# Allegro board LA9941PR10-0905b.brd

Outline 291.1 x 129.75 mm; copper layers: TOP, GND1, IN1, VCC, IN2, IN3, GND2, IN4, GND3, BOTTOM. Coordinates in mm from the lower left corner of the outline.

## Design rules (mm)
net group 8: nets DISP_CEC DISPOFF#
net group 10: nets AUD_SPK_L+ AUD_SPK_R+
net group AC: nets ACN ACP
net group CLK_27M: nets CLK_27M_IN CLK_27M_OUT
net group CSO_B: nets CSON_B CSOP_B
net group CSS_1: nets CSSN_1 CSSP_1
net group DDRA_CTRL: nets DDR_CS0_DIMMA# DDR_CS1_DIMMA#
net group DIFFPAIR0: nets DDC_CLK_HDMI DDC_DAT_HDMI
net group DIFFPAIR32: nets MDP_A3N_CPU MDP_A3P_CPU
net group DIFFPAIR33: nets MDP_A2N_CPU MDP_A2P_CPU
net group DIFFPAIR34: nets MDP_A1N_CPU MDP_A1P_CPU
net group DISP_C_A1: nets DISP_C_A1N DISP_C_A1P
net group DISP_C_A2: nets DISP_C_A2N DISP_C_A2P
net group DISP_C_A3: nets DISP_C_A3N DISP_C_A3P
net group EC_SMB_DA1: nets EC_SMB_CK1 EC_SMB_DA1
net group EDP_TX2: nets EDP_TXN2 EDP_TXP2
net group EDP_TX2_C: nets EDP_TXN2_C EDP_TXP2_C
net group EDP_TX2_R: nets EDP_TXN2_R EDP_TXP2_R
net group EDP_TX3: nets EDP_TXN3 EDP_TXP3
net group EDP_TX3_C: nets EDP_TXN3_C EDP_TXP3_C
net group EDP_TX3_R: nets EDP_TXN3_R EDP_TXP3_R
net group ISUM: nets ISUMN ISUMP
net group MDP_A0_R: nets MDP_A0N_R MDP_A0P_R
net group MDP_A1_R: nets MDP_A1N_R MDP_A1P_R
net group MDP_A2_R: nets MDP_A2N_R MDP_A2P_R
net group MDP_A3_R: nets MDP_A3N_R MDP_A3P_R
net group PCH_SMBCLK: nets PCH_SMBCLK PCH_SMBDATA
net group SR: nets SRN SRP
net group USB3R1_8723: nets USB3RN1_8723 USB3RP1_8723
net group USB3R1_C: nets USB3RN1_C USB3RP1_C
net group USB3R2_8723: nets USB3RN2_8723 USB3RP2_8723
net group USB3R2_C: nets USB3RN2_C USB3RP2_C
net group USB3RN4: nets USB3RN4 USB3RP4
net group USB3T1_8723: nets USB3TN1_8723 USB3TP1_8723
net group USB3T1_C: nets USB3TN1_C USB3TP1_C
net group USB3T2_8723: nets USB3TN2_8723 USB3TP2_8723
net group USB3T2_C: nets USB3TN2_C USB3TP2_C
net group USB3TN4: nets USB3TN4 USB3TP4
net group VSSSEN: nets VCCSENSE VSSSENSE
net group 15: nets CLK_CPU_ITP CLK_CPU_ITP# CLK_PCIE_CD CLK_PCIE_CD# CLK_PCIE_MINI3 CLK_PCIE_MINI3# CLKIN_DMI CLKIN_DMI# CLKIN_DOT96 CLKIN_DOT96# CLKIN_SATA CLKIN_SATA# EDP_COMP EDP_HPD EDP_HPD_S EDP_LVDDEN EDP_PWM FDI_INT TMDS_L_TXCP USBRBIAS
net group 20: nets SPK_L+ SPK_L- SPK_R+ SPK_R-
net group 50H: nets CLK_PCH_14M DDR_A_D0 DDR_A_D1 DDR_A_D2 DDR_A_D3 DDR_A_D4 DDR_A_D5 DDR_A_D6 DDR_A_D7 DDR_A_D8 DDR_A_D9 DDR_A_D10 DDR_A_D11 DDR_A_D12 DDR_A_D13 DDR_A_D14 DDR_A_D15 DDR_A_D16 DDR_A_D17 DDR_A_D18 DDR_A_D19 DDR_A_D20 DDR_A_D21 DDR_A_D22 DDR_A_D23 DDR_A_D24 DDR_A_D25 DDR_A_D26 DDR_A_D27 DDR_A_D28 DDR_A_D29 DDR_A_D30 DDR_A_D31 DDR_A_D32 DDR_A_D33 DDR_A_D34 DDR_A_D35 DDR_A_D36 DDR_A_D37 DDR_A_D38 DDR_A_D39 DDR_A_D40 DDR_A_D41 DDR_A_D42 DDR_A_D43 DDR_A_D44 DDR_A_D45 DDR_A_D46 DDR_A_D47 DDR_A_D48 DDR_A_D49 DDR_A_D50 DDR_A_D51 DDR_A_D52 DDR_A_D53 DDR_A_D54 DDR_A_D55 DDR_A_D56 DDR_A_D57 DDR_A_D58 DDR_A_D59 DDR_A_D60 DDR_A_D61 DDR_A_D62 DDR_A_D63 DDR_B_D0 DDR_B_D1 DDR_B_D2 DDR_B_D3 DDR_B_D4 DDR_B_D5 DDR_B_D6 DDR_B_D7 DDR_B_D8 DDR_B_D9 DDR_B_D10 DDR_B_D11 DDR_B_D12 DDR_B_D13 DDR_B_D14 DDR_B_D15 DDR_B_D16 DDR_B_D17 DDR_B_D18 DDR_B_D19 DDR_B_D20 DDR_B_D21 DDR_B_D22 DDR_B_D23 DDR_B_D24 DDR_B_D25 DDR_B_D26 DDR_B_D27 DDR_B_D28 DDR_B_D29 DDR_B_D30 DDR_B_D31 DDR_B_D32 DDR_B_D33 DDR_B_D34 DDR_B_D35 DDR_B_D36 DDR_B_D37 DDR_B_D38 DDR_B_D39 DDR_B_D40 DDR_B_D41 DDR_B_D42 DDR_B_D43 DDR_B_D44 DDR_B_D45 DDR_B_D46 DDR_B_D47 DDR_B_D48 DDR_B_D49 DDR_B_D50 DDR_B_D51 DDR_B_D52 DDR_B_D53 DDR_B_D54 DDR_B_D55 DDR_B_D56 DDR_B_D57 DDR_B_D58 DDR_B_D59 DDR_B_D60 DDR_B_D61 DDR_B_D62 DDR_B_D63 DSWODVREN H_CPU_SVIDALRT# H_PROCHOT#_EC H_PROCHOT#_R H_THERMTRIP#_C HDA_BIT_CLK HDA_BITCLK_AUDIO HDA_RST# HDA_RST_AUDIO# HDA_SDIN0 HDA_SDO HDA_SDOUT HDA_SDOUT_AUDIO HDA_SPKR HDA_SYNC HDA_SYNC_AUDIO KB_RST# LPC_AD0 LPC_AD1 LPC_AD2 LPC_AD3 LPC_FRAME# PBTN_OUT# PCH_INTVRMEN PCH_RSMRST# PCH_SPI_CS1# PCH_SPI_HOLD# PCH_SPI_WP# SM_INTRUDER# SYS_PWROK WAKE# XDP_DBRESET#
net group ASY: nets CPU_PLTRST# H_CPUPWRGD H_PM_SYNC H_PROCHOT# H_THERMTRIP# PM_DRAM_PWRGD PM_SYS_PWRGD_BUF PM_SYS_PWRGD_BUF_R
net group DDR-CMD/CTL_12/18: nets DDR_A_BS0 DDR_A_BS1 DDR_A_BS2 DDR_A_CAS# DDR_A_MA0 DDR_A_MA1 DDR_A_MA2 DDR_A_MA3 DDR_A_MA4 DDR_A_MA5 DDR_A_MA6 DDR_A_MA7 DDR_A_MA8 DDR_A_MA9 DDR_A_MA10 DDR_A_MA11 DDR_A_MA12 DDR_A_MA13 DDR_A_MA14 DDR_A_MA15 DDR_A_RAS# DDR_A_WE# DDR_B_BS0 DDR_B_BS1 DDR_B_BS2 DDR_B_CAS# DDR_B_MA0 DDR_B_MA1 DDR_B_MA2 DDR_B_MA3 DDR_B_MA4 DDR_B_MA5 DDR_B_MA6 DDR_B_MA7 DDR_B_MA8 DDR_B_MA9 DDR_B_MA10 DDR_B_MA11 DDR_B_MA12 DDR_B_MA13 DDR_B_MA14 DDR_B_MA15 DDR_B_RAS# DDR_B_WE# DDR_CKE0_DIMMA DDR_CKE1_DIMMA DDR_CKE2_DIMMB DDR_CKE3_DIMMB DDR_CS2_DIMMB# DDR_CS3_DIMMB# M_ODT0 M_ODT1 M_ODT2 M_ODT3
net group DDR_CLK: nets M_CLK_DDR0 M_CLK_DDR1 M_CLK_DDR2 M_CLK_DDR3 M_CLK_DDR#0 M_CLK_DDR#1 M_CLK_DDR#2 M_CLK_DDR#3
net group DDR_DQS: nets DDR_A_DQS0 DDR_A_DQS1 DDR_A_DQS2 DDR_A_DQS3 DDR_A_DQS4 DDR_A_DQS5 DDR_A_DQS6 DDR_A_DQS7 DDR_A_DQS#0 DDR_A_DQS#1 DDR_A_DQS#2 DDR_A_DQS#3 DDR_A_DQS#4 DDR_A_DQS#5 DDR_A_DQS#6 DDR_A_DQS#7 DDR_B_DQS0 DDR_B_DQS1 DDR_B_DQS2 DDR_B_DQS3 DDR_B_DQS4 DDR_B_DQS5 DDR_B_DQS6 DDR_B_DQS7 DDR_B_DQS#0 DDR_B_DQS#1 DDR_B_DQS#2 DDR_B_DQS#3 DDR_B_DQS#4 DDR_B_DQS#5 DDR_B_DQS#6 DDR_B_DQS#7
net group DIFFPAIR35: nets MDP_A0P_CPU
net group DMI: nets DMI_CRX_PTX_N0 DMI_CRX_PTX_N1 DMI_CRX_PTX_N2 DMI_CRX_PTX_N3 DMI_CRX_PTX_P0 DMI_CRX_PTX_P1 DMI_CRX_PTX_P2 DMI_CRX_PTX_P3 DMI_CTX_PRX_N0 DMI_CTX_PRX_N1 DMI_CTX_PRX_N2 DMI_CTX_PRX_N3 DMI_CTX_PRX_P0 DMI_CTX_PRX_P1 DMI_CTX_PRX_P2 DMI_CTX_PRX_P3
net group DP: nets DISP_A0N_R DISP_A0P_R DISP_A1N_R DISP_A1P_R DISP_A2N_R DISP_A2P_R DISP_A3N_R DISP_A3P_R DISP_C_A0N DISP_C_A0P DISP_CLK_AUXP_CONN DISP_DAT_AUXN_CONN MDP_A0N_CPU MDP_AUXN_PCH MDP_AUXN_PCH_C MDP_AUXP_PCH MDP_AUXP_PCH_C
net group EDP: nets EDP_AUXN EDP_AUXN_R EDP_AUXP EDP_AUXP_R EDP_TXN0 EDP_TXN0_C EDP_TXN0_R EDP_TXN1 EDP_TXN1_C EDP_TXN1_R EDP_TXP0 EDP_TXP0_C EDP_TXP0_R EDP_TXP1 EDP_TXP1_C EDP_TXP1_R
net group GREEN CLK: nets XTAL25_IN
net group HDMI: nets HDMI_A0N_VGA HDMI_A0P_VGA HDMI_A1N_VGA HDMI_A1P_VGA HDMI_A2N_VGA HDMI_A2P_VGA HDMI_A3N_VGA HDMI_A3P_VGA HDMI_CEC HDMI_DDB_CTRLCLK HDMI_DDB_CTRLDATA HDMI_HPLUG HDMI_RESERVED TMDS_L_TX0N TMDS_L_TX0P TMDS_L_TX1N TMDS_L_TX1P TMDS_L_TX2N TMDS_L_TX2P TMDS_L_TXCN TMDS_RD_TX0N TMDS_RD_TX0P TMDS_RD_TX1N TMDS_RD_TX1P TMDS_RD_TX2N TMDS_RD_TX2P TMDS_RD_TXCN TMDS_RD_TXCP TMDS_TX0N TMDS_TX0P TMDS_TX1N TMDS_TX1P TMDS_TX2N TMDS_TX2P TMDS_TXCN TMDS_TXCP
net group KB: nets KB_CAPS_LED KB_DET# KSI0 KSI1 KSI2 KSI3 KSI4 KSI5 KSI6 KSI7 KSO0 KSO1 KSO2 KSO3 KSO4 KSO5 KSO6 KSO7 KSO8 KSO9 KSO10 KSO11 KSO12 KSO13 KSO14 KSO15 KSO16
net group PCIE: nets PCIE_PRX_CARDTX_N4 PCIE_PRX_CARDTX_P4 PCIE_PRX_WLANTX_N3 PCIE_PRX_WLANTX_P3 PCIE_PTX_CARDRX_N4 PCIE_PTX_CARDRX_N4_C PCIE_PTX_CARDRX_P4 PCIE_PTX_CARDRX_P4_C PCIE_PTX_WLANRX_N3 PCIE_PTX_WLANRX_N3_C PCIE_PTX_WLANRX_P3 PCIE_PTX_WLANRX_P3_C
net group PECI: nets H_PECI
net group PEG: nets PEG_GTX_C_HRX_N0 PEG_GTX_C_HRX_N1 PEG_GTX_C_HRX_N2 PEG_GTX_C_HRX_N3 PEG_GTX_C_HRX_N4 PEG_GTX_C_HRX_N5 PEG_GTX_C_HRX_N6 PEG_GTX_C_HRX_N7 PEG_GTX_C_HRX_N8 PEG_GTX_C_HRX_N9 PEG_GTX_C_HRX_N10 PEG_GTX_C_HRX_N11 PEG_GTX_C_HRX_N12 PEG_GTX_C_HRX_N13 PEG_GTX_C_HRX_N14 PEG_GTX_C_HRX_N15 PEG_GTX_C_HRX_P0 PEG_GTX_C_HRX_P1 PEG_GTX_C_HRX_P2 PEG_GTX_C_HRX_P3 PEG_GTX_C_HRX_P4 PEG_GTX_C_HRX_P5 PEG_GTX_C_HRX_P6 PEG_GTX_C_HRX_P7 PEG_GTX_C_HRX_P8 PEG_GTX_C_HRX_P9 PEG_GTX_C_HRX_P10 PEG_GTX_C_HRX_P11 PEG_GTX_C_HRX_P12 PEG_GTX_C_HRX_P13 PEG_GTX_C_HRX_P14 PEG_GTX_C_HRX_P15 PEG_GTX_HRX_N0 PEG_GTX_HRX_N1 PEG_GTX_HRX_N2 PEG_GTX_HRX_N3 PEG_GTX_HRX_N4 PEG_GTX_HRX_N5 PEG_GTX_HRX_N6 PEG_GTX_HRX_N7 PEG_GTX_HRX_N8 PEG_GTX_HRX_N9 PEG_GTX_HRX_N10 PEG_GTX_HRX_N11 PEG_GTX_HRX_N12 PEG_GTX_HRX_N13 PEG_GTX_HRX_N14 PEG_GTX_HRX_N15 PEG_GTX_HRX_P0 PEG_GTX_HRX_P1 PEG_GTX_HRX_P2 PEG_GTX_HRX_P3 PEG_GTX_HRX_P4 PEG_GTX_HRX_P5 PEG_GTX_HRX_P6 PEG_GTX_HRX_P7 PEG_GTX_HRX_P8 PEG_GTX_HRX_P9 PEG_GTX_HRX_P10 PEG_GTX_HRX_P11 PEG_GTX_HRX_P12 PEG_GTX_HRX_P13 PEG_GTX_HRX_P14 PEG_GTX_HRX_P15 PEG_HTX_C_GRX_N0 PEG_HTX_C_GRX_N1 PEG_HTX_C_GRX_N2 PEG_HTX_C_GRX_N3 PEG_HTX_C_GRX_N4 PEG_HTX_C_GRX_N5 PEG_HTX_C_GRX_N6 PEG_HTX_C_GRX_N7 PEG_HTX_C_GRX_N8 PEG_HTX_C_GRX_N9 PEG_HTX_C_GRX_N10 PEG_HTX_C_GRX_N11 PEG_HTX_C_GRX_N12 PEG_HTX_C_GRX_N13 PEG_HTX_C_GRX_N14 PEG_HTX_C_GRX_N15 PEG_HTX_C_GRX_P0 PEG_HTX_C_GRX_P1 PEG_HTX_C_GRX_P2 PEG_HTX_C_GRX_P3 PEG_HTX_C_GRX_P4 PEG_HTX_C_GRX_P5 PEG_HTX_C_GRX_P6 PEG_HTX_C_GRX_P7 PEG_HTX_C_GRX_P8 PEG_HTX_C_GRX_P9 PEG_HTX_C_GRX_P10 PEG_HTX_C_GRX_P11 PEG_HTX_C_GRX_P12 PEG_HTX_C_GRX_P13 PEG_HTX_C_GRX_P14 PEG_HTX_C_GRX_P15 PEG_HTX_GRX_N0 PEG_HTX_GRX_N1 PEG_HTX_GRX_N2 PEG_HTX_GRX_N3 PEG_HTX_GRX_N4 PEG_HTX_GRX_N5 PEG_HTX_GRX_N6 PEG_HTX_GRX_N7 PEG_HTX_GRX_N8 PEG_HTX_GRX_N9 PEG_HTX_GRX_N10 PEG_HTX_GRX_N11 PEG_HTX_GRX_N12 PEG_HTX_GRX_N13 PEG_HTX_GRX_N14 PEG_HTX_GRX_N15 PEG_HTX_GRX_P0 PEG_HTX_GRX_P1 PEG_HTX_GRX_P2 PEG_HTX_GRX_P3 PEG_HTX_GRX_P4 PEG_HTX_GRX_P5 PEG_HTX_GRX_P6 PEG_HTX_GRX_P7 PEG_HTX_GRX_P8 PEG_HTX_GRX_P9 PEG_HTX_GRX_P10 PEG_HTX_GRX_P11 PEG_HTX_GRX_P12 PEG_HTX_GRX_P13 PEG_HTX_GRX_P14 PEG_HTX_GRX_P15
net group PLATFORM CLK: nets CLK_CPU_DMI CLK_CPU_DMI# CLK_CPU_SSC_DPLL CLK_CPU_SSC_DPLL# CLK_PCI0 CLK_PCI1 CLK_PCI2 CLK_PCI_DEBUG CLK_PCI_LPBACK CLK_PCI_LPC CLK_PCI_TPM CLK_PCI_TPM_R CLK_PEG_VGA CLK_PEG_VGA# DPLL_REF_CLK DPLL_REF_CLK#
net group PWR: nets +0.675VS +0.675VSP +1.2V_5505SWR +1.2V_5505SWR_S +1.5V_RUN_B+ +1.05VM_VCCASW +1.05VM_VCCSUS1 +1.05VM_VCCSUS2 +1.5VS +1.05VS_VCCCORE +1.05VSDGPU +1.5VSDGPU +1.35V +1.35V_CPU_VDDQ +1.35V_MEN_P +1.35V_PWROK +2.5V_5505LDO_S +3.3V_RUN_VDD33 +3V_MSATA +3V_NFC +3V_PCH +3V_PS8723 +3V_THERMAL +3V_VCCPSPI +3VALW +3VALW_EC +3VALWP +3VLP +3VS_DELAY +3VS_DP +3VS_MDPR +5V_HDMI_DDC +5VALWP +5VS_HDD +5VS_KBL +CLK_PLLVDD +EC_VCCA +EDPVDD +FB_VREF +FBA_PLL_AVDD +FBA_VREFC_H +FBA_VREFC_L +FBA_VREFD_H +FBA_VREFD_L +FBB_VREFC_H +FBB_VREFC_L +FBB_VREFD_H +FBB_VREFD_L +INV_PWR_SRC +LCDVDD_R +MIC1_VREFO +PCH_USB_DCPSUS3 +PCH_VCC +PCH_VCCASW +PCH_VCCCFUSE +PCH_VCCCLK +PCH_VCCCLK3_3 +PCH_VCCDSW +PCH_VCCDSW_R +PCH_VPROC +PLLVDD +RTCBATT +RTCVCC +V1.05S_VCCP_PWRGOOD +V1.05V_B+ +V18R +V_DDR_REF +V_DDR_REFA_R +V_DDR_REFB_R +V_SM_VREF +VCC_PWR_SRC1 +VCC_PWR_SRC2 +VCCAFDI_VRM +VCCIO2PCH +VCCIO_OUT +VCCIOA_OUT +VCCRTCEXT +VCCSST +VCHGR +VDDA +VDISPLAY_VCC +VGA_B+ +VLDOIN_1.35V +VSBP +VSBP_AMP_AVCC +VSBP_AMP_PVCC
net group RTC: nets PCH_RTCRST# PCH_RTCX1 PCH_RTCX2 PCH_SRTCRST#
net group SATA: nets SATA_PRX_DTX_N0 SATA_PRX_DTX_N0_C SATA_PRX_DTX_N0_RC SATA_PRX_DTX_N0_RC1 SATA_PRX_DTX_N1 SATA_PRX_DTX_P0 SATA_PRX_DTX_P0_C SATA_PRX_DTX_P0_RC SATA_PRX_DTX_P0_RC1 SATA_PRX_DTX_P1 SATA_PTX_DRX_N0 SATA_PTX_DRX_N0_C SATA_PTX_DRX_N0_RC SATA_PTX_DRX_N0_RC1 SATA_PTX_DRX_N1 SATA_PTX_DRX_N1_C SATA_PTX_DRX_P0 SATA_PTX_DRX_P0_C SATA_PTX_DRX_P0_RC SATA_PTX_DRX_P0_RC1 SATA_PTX_DRX_P1 SATA_PTX_DRX_P1_C
net group SPI: nets PCH_SPI_CLK PCH_SPI_CS# PCH_SPI_SI PCH_SPI_SO
net group SVID: nets VR_SVID_ALRT# VR_SVID_CLK VR_SVID_DAT
net group USB2.0: nets USB20_N0 USB20_N1 USB20_N2 USB20_N3 USB20_N4 USB20_N9 USB20_N9_R USB20_N12 USB20_P0 USB20_P1 USB20_P2 USB20_P3 USB20_P4 USB20_P9_R USB20_P12 USBP0_D+ USBP0_D- USBP0_R_D+ USBP0_R_D- USBP1_D+ USBP1_D- USBP1_R_D+ USBP1_R_D-
net group USB3.0: nets USB3RN1 USB3RN1_D- USB3RN2 USB3RN2_D- USB3RN3 USB3RP1 USB3RP1_D+ USB3RP2 USB3RP2_D+ USB3RP3 USB3T_N1 USB3T_N2 USB3T_P1 USB3T_P2 USB3TN1 USB3TN1_D- USB3TN2 USB3TN2_D- USB3TN3 USB3TP1 USB3TP1_D+ USB3TP2 USB3TP2_D+ USB3TP3
net group USB20_N9: nets USB20_P9
net group VRAM-CMD_10_25: nets FBA_CMD0 FBA_CMD1 FBA_CMD2 FBA_CMD3 FBA_CMD4 FBA_CMD5 FBA_CMD6 FBA_CMD7 FBA_CMD8 FBA_CMD9 FBA_CMD10 FBA_CMD11 FBA_CMD12 FBA_CMD13 FBA_CMD14 FBA_CMD15 FBA_CMD16 FBA_CMD17 FBA_CMD18 FBA_CMD19 FBA_CMD20 FBA_CMD21 FBA_CMD22 FBA_CMD23 FBA_CMD24 FBA_CMD25 FBA_CMD26 FBA_CMD27 FBA_CMD28 FBA_CMD29 FBA_CMD30 FBA_CMD31 FBB_CMD0 FBB_CMD1 FBB_CMD2 FBB_CMD3 FBB_CMD4 FBB_CMD5 FBB_CMD6 FBB_CMD7 FBB_CMD8 FBB_CMD9 FBB_CMD10 FBB_CMD11 FBB_CMD12 FBB_CMD13 FBB_CMD14 FBB_CMD15 FBB_CMD16 FBB_CMD17 FBB_CMD18 FBB_CMD19 FBB_CMD20 FBB_CMD21 FBB_CMD22 FBB_CMD23 FBB_CMD24 FBB_CMD25 FBB_CMD26 FBB_CMD27 FBB_CMD28 FBB_CMD29 FBB_CMD30 FBB_CMD31
net group VRAM-DQ/CLK_10_25: nets CLKA0 CLKA0# CLKA1 CLKA1# CLKB0 CLKB0# CLKB1 CLKB1# FBA_D0 FBA_D1 FBA_D2 FBA_D3 FBA_D4 FBA_D5 FBA_D6 FBA_D7 FBA_D8 FBA_D9 FBA_D10 FBA_D11 FBA_D12 FBA_D13 FBA_D14 FBA_D15 FBA_D16 FBA_D17 FBA_D18 FBA_D19 FBA_D20 FBA_D21 FBA_D22 FBA_D23 FBA_D24 FBA_D25 FBA_D26 FBA_D27 FBA_D28 FBA_D29 FBA_D30 FBA_D31 FBA_D32 FBA_D33 FBA_D34 FBA_D35 FBA_D36 FBA_D37 FBA_D38 FBA_D39 FBA_D40 FBA_D41 FBA_D42 FBA_D43 FBA_D44 FBA_D45 FBA_D46 FBA_D47 FBA_D48 FBA_D49 FBA_D50 FBA_D51 FBA_D52 FBA_D53 FBA_D54 FBA_D55 FBA_D56 FBA_D57 FBA_D58 FBA_D59 FBA_D60 FBA_D61 FBA_D62 FBA_D63 FBA_DBI0 FBA_DBI1 FBA_DBI2 FBA_DBI3 FBA_DBI4 FBA_DBI5 FBA_DBI6 FBA_DBI7 FBA_EDC0 FBA_EDC1 FBA_EDC2 FBA_EDC3 FBA_EDC4 FBA_EDC5 FBA_EDC6 FBA_EDC7 FBB_D0 FBB_D1 FBB_D2 FBB_D3 FBB_D4 FBB_D5 FBB_D6 FBB_D7 FBB_D8 FBB_D9 FBB_D10 FBB_D11 FBB_D12 FBB_D13 FBB_D14 FBB_D15 FBB_D16 FBB_D17 FBB_D18 FBB_D19 FBB_D20 FBB_D21 FBB_D22 FBB_D23 FBB_D24 FBB_D25 FBB_D26 FBB_D27 FBB_D28 FBB_D29 FBB_D30 FBB_D31 FBB_D32 FBB_D33 FBB_D34 FBB_D35 FBB_D36 FBB_D37 FBB_D38 FBB_D39 FBB_D40 FBB_D41 FBB_D42 FBB_D43 FBB_D44 FBB_D45 FBB_D46 FBB_D47 FBB_D48 FBB_D49 FBB_D50 FBB_D51 FBB_D52 FBB_D53 FBB_D54 FBB_D55 FBB_D56 FBB_D57 FBB_D58 FBB_D59 FBB_D60 FBB_D61 FBB_D62 FBB_D63 FBB_DBI0 FBB_DBI1 FBB_DBI2 FBB_DBI3 FBB_DBI4 FBB_DBI5 FBB_DBI6 FBB_DBI7 FBB_EDC0 FBB_EDC1 FBB_EDC2 FBB_EDC3 FBB_EDC4 FBB_EDC5 FBB_EDC6 FBB_EDC7
net group VRAM-WCK_15/10_25: nets FBA_WCK01 FBA_WCK01# FBA_WCK23 FBA_WCK23# FBA_WCK45 FBA_WCK45# FBA_WCK67 FBA_WCK67# FBB_WCK23 FBB_WCK23# FBB_WCK45 FBB_WCK45# FBB_WCK67 FBB_WCK67#
nets with their own width: min track width 0.254; nets BAT1 BAT2 BAT3 BAT4 BAT5 BATT_LOW_LED#_D GPU_VDD_SENSE GPU_VSS_SENSE IBAT1 IBAT2 IBAT3 IBAT4 IBAT5 SENSE_B#
nets with their own width: min track width 0.305; nets PEG_COMP
nets with their own width: min track width 0.381; nets SM_RCOMP0 SM_RCOMP1 SM_RCOMP2
nets with their own width: min track width 0.508; nets +3VS_RD +5VALW +5VS +FBA_DLL_AVDD +GPU_CORE +VCC_CORE +VCCP AGND B+ B++ ECAGND GND KB_BL_PWM N6647607 N97573639 N98184072 N112583857 N114414277 VIN
nets with their own width: min track width 1.524; nets +3VS N112208327
nets with their own width: min track width 2.032; nets +5V_CHGUSB_1 +5V_CHGUSB_3

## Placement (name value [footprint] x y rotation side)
ADP100  -  [ACES_50290-00701-001_7P-T]  22.9 92.06 0 bottom
BAT100  -  [ACES_50290-01201-P01_12P-T]  108.4 20.14 180 bottom
C1  -  [C_0402]  198.2 17.56 180 top
C2  -  [C_0402]  198.2 18.45 180 top
C3  -  [C_0402]  198 13.85 180 top
C4  -  [C_0402]  207.77 14.5 270 top
C5  -  [C_0402]  207.89 17.62 0 top
C6  -  [C_0402]  208.42 20.45 180 top
C8  -  [C_0402]  207.89 16.48 0 top
C11  -  [C_0603]  217.04 21.8 180 bottom
C12  -  [C_0603]  226.06 23.06 270 bottom
C13  -  [C_0402]  218.31 20.51 90 top
C14  -  [C_0402]  218.31 22.66 90 top
C15  -  [C_0402]  215.01 21.42 270 top
C16  -  [C_0402]  215.01 22.66 90 top
C17  -  [C_0402]  10.07 84.35 90 top
C18  -  [C_0402]  9.17 86.14 0 top
C37  -  [C_0402]  26.95 80.91 0 top
C38  -  [C_0402]  30.4 77.74 180 top
C42  -  [C_0402]  29.72 84.16 270 bottom
C43  -  [C_0402]  25.18 75.27 270 top
C47  -  [C_0402]  30.61 84.16 270 bottom
C48  -  [C_0402]  30.4 80.72 180 top
C53  -  [C_0402]  28.83 84.16 270 bottom
C54  -  [C_0402]  22 83.07 0 bottom
C56  -  [C_0402]  22 82.18 0 bottom
C57  -  [C_0402]  22 84.02 0 bottom
C59  -  [C_0402]  22 84.98 0 bottom
C93  -  [C_0402]  31.5 84.16 270 bottom
C1135  -  [C_0402]  122.49 21.08 90 bottom
C2020  -  [C_0402]  25.18 76.14 90 top
C2021  -  [C_0402]  30.39 76.67 270 top
CA3  -  [C_0805]  33.58 36.46 0 top
CA4  -  [C_0402]  34.38 38.41 0 top
CA5  -  [C_0805]  19.56 51.26 180 top
CA6  -  [C_0402]  19.89 45.54 180 top
CA7  -  [C_0402]  28.92 41.16 180 bottom
CA8  -  [C_0603]  26.45 44.4 90 bottom
CA9  -  [C_0402]  27.53 45.24 270 bottom
CA10  -  [C_0402]  23.43 38.54 90 bottom
CA11  -  [C_0603]  22.29 40.08 270 bottom
CA12  -  [C_0805]  19.56 53.04 180 top
CA13  -  [C_0402]  22.67 46.49 0 bottom
CA14  -  [C_0805]  19.34 39.4 270 top
CA15  -  [C_0402]  23.01 45.16 0 bottom
CA16  -  [C_0603]  23.11 36.58 0 top
CA17  -  [C_0402]  29.86 39.11 0 top
CA18  -  [C_0805]  25.37 39 0 bottom
CA19  -  [C_0402]  24.32 38.54 90 bottom
CA20  -  [C_0402]  24.41 46.49 0 bottom
CA21  -  [C_0805]  26.37 43 0 bottom
CA22  -  [C_0402]  5.45 35.69 0 top
CA23  -  [C_0402]  31.65 45.16 0 top
CA24  -  [C_0402]  26.42 36.97 270 top
CA25  -  [C_0402]  25.53 36.97 270 top
CA26  -  [C_B2]  20.08 39.58 270 bottom
CA27  -  [C_0402]  31.65 43.89 0 top
CA28  -  [C_0402]  9.32 34.77 0 bottom
CA29  -  [C_0402]  9.32 33.73 0 bottom
CA30  -  [C_0402]  31.72 35.57 180 top
CA31  -  [C_0805]  7.54 32.67 0 top
CA32  -  [C_0402]  29.73 38.23 0 bottom
CA33  -  [C_0402]  14.86 37.22 0 top
CA34  -  [C_0402]  17.72 45.99 180 top
CA37  -  [C_0402]  17.55 37.22 180 top
CA38  -  [C_0402]  15.05 45.99 0 top
CA39  -  [C_0402]  31.43 40.95 180 top
CA41  -  [C_0402]  3.4 22.5 270 bottom
CA42  -  [C_0402]  4.29 22.5 270 bottom
CA43  -  [C_0805]  13.31 20.49 270 top
CA45  -  [C_0805]  9.69 20.56 90 top
CA46  -  [C_0805]  7.91 20.56 90 top
CA53  -  [C_0402]  6.98 31.33 270 bottom
CA54  -  [C_0603]  6.6 11.82 180 bottom
CA55  -  [C_0603]  2.79 11.82 0 bottom
CA56  -  [C_0603]  9.65 8.96 180 top
CA57  -  [C_0603]  7.11 10.24 270 top
CA58  -  [C_0402]  7.94 31.33 270 bottom
CA59  -  [C_0402]  13.52 31.33 270 bottom
CA60  -  [C_0402]  12.57 31.33 270 bottom
CA61  -  [C_0603]  5.23 20.81 0 bottom
CA62  -  [C_0603]  9.52 20.9 180 bottom
CA63  -  [C_0402]  15.57 20.26 180 top
CA64  -  [C_0603]  15.94 23.76 270 bottom
CA65  -  [C_0402]  17.51 20.27 180 top
CA66  -  [C_0805]  30.65 33.06 270 top
CA67  -  [C_0805]  19.98 17.98 0 top
CA68  -  [C_0603]  16.95 42.36 90 top
CA69  -  [C_0603]  16.95 41.35 270 top
CA71  -  [C_0603]  12.77 30.99 0 top
CA72  -  [C_0603]  14.67 20.45 180 bottom
CA73  -  [C_0603]  10.49 19.79 0 bottom
CA75  -  [C_0603]  11.49 30.49 90 bottom
CA76  -  [C_0603]  10.22 30.49 90 bottom
CA77  -  [C_0402]  19.35 19.31 0 top
CA78  -  [C_0603]  21.46 19.5 0 top
CA79  -  [C_0402]  19.35 20.26 0 top
CA80  -  [C_0402]  22.87 20.65 180 top
CA81  -  [C_0402]  33.25 32.28 270 top
CA82  -  [C_0603]  32.17 31.25 90 top
CA83  -  [C_0402]  16.31 29.15 0 bottom
CA84  -  [C_0603]  22.76 32.27 180 top
CA85  -  [C_0805]  30.61 28.49 90 top
CA86  -  [C_0805]  18.02 20.05 180 bottom
CA87  -  [C_0402]  25.4 31.39 270 top
CA88  -  [C_0805]  32.38 28.49 90 top
CA89  -  [C_0402]  18.11 21.53 180 bottom
CA90  -  [C_0805]  28.08 27.31 180 top
CA91  -  [C_0402]  17.64 34.42 0 top
CA92  -  [C_0402]  24.51 31.39 270 top
CA93  -  [C_0402]  26.27 29.22 0 top
CA94  -  [C_0402]  28.26 25.74 270 top
CA95  -  [C_0402]  26.21 24.82 0 top
CA96  -  [C_0402]  26.15 22.42 0 top
CA97  -  [C_0402]  25.28 22.42 180 top
CD2  -  [C_0402]  108.95 31.76 0 top
CD3  -  [C_0402]  146.72 23.3 180 bottom
CD4  -  [C_0402]  136.74 21.98 180 bottom
CD5  -  [C_0402]  146.05 33.84 90 top
CD6  -  [C_0402]  135.32 33.84 90 top
CD7  -  [C_SX]  164.46 64.53 180 bottom
CD8  -  [C_0603]  133.54 33.66 90 top
CD9  -  [C_0603]  142.56 33.66 90 top
CD10  -  [C_0603]  141.22 23.1 180 bottom
CD11  -  [C_0603]  137.03 23.1 180 bottom
CD12  -  [C_0603]  138.81 33.66 90 top
CD13  -  [C_0603]  147.24 22.16 180 bottom
CD16  -  [C_0402]  150.81 23.96 90 top
CD17  -  [C_0402]  173.21 34.62 0 top
CD18  -  [C_0402]  173.21 33.73 0 top
CD19  -  [C_0402]  173.4 25.34 0 top
CD20  -  [C_0402]  173.4 26.23 0 top
CD21  -  [C_0402]  170.57 34.87 180 top
CD22  -  [C_0603]  170.56 33.79 180 top
CD24  -  [C_0402]  183.06 33.35 0 top
CD25  -  [C_0402]  220.91 25.59 90 top
CD26  -  [C_0402]  208.28 25.52 90 top
CD27  -  [C_0402]  222.44 33.65 90 top
CD28  -  [C_0402]  207.33 34.5 270 top
CD30  -  [C_0603]  216.28 25.6 90 top
CD31  -  [C_0603]  219.71 25.6 90 top
CD32  -  [C_0603]  212.05 26.06 90 top
CD33  -  [C_0603]  216.15 33.66 90 top
CD34  -  [C_0603]  220.6 33.54 90 top
CD35  -  [C_0603]  211.64 33.6 90 top
CD38  -  [C_0402]  224.39 25.34 0 top
CD39  -  [C_0402]  246.52 26.68 180 top
CD40  -  [C_0402]  246.52 27.63 180 top
CD41  -  [C_0402]  246.65 30.61 180 top
CD42  -  [C_0402]  246.65 31.57 180 top
CD43  -  [C_0402]  244.22 34.95 270 top
CD44  -  [C_0603]  245.43 37.16 90 top
CE4  -  [C_0402]  165.93 14.74 180 bottom
CE5  -  [C_0402]  166.81 21.33 90 bottom
CE6  -  [C_0402]  166.86 20.45 0 bottom
CE7  -  [C_0402]  166 16.33 180 bottom
CE8  -  [C_0402]  164.99 21.35 90 bottom
CE9  -  [C_0402]  165.92 21.33 90 bottom
CE10  -  [C_0402]  159.26 21.74 270 top
CE11  -  [C_0402]  172.39 16.84 0 top
CE12  -  [C_0402]  160.57 25.21 180 top
CE13  -  [C_0402]  157.4 19.69 0 top
CE14  -  [C_0402]  165.92 24.34 270 top
CE15  -  [C_0402]  148.02 16.7 90 bottom
CE16  -  [C_0402]  157.96 16.9 180 bottom
CE17  -  [C_0805]  168.21 13.05 270 top
CE18  -  [C_0402]  165.81 12.97 0 top
CE19  -  [C_0402]  155.26 17.74 270 bottom
CE20  -  [C_0402]  151.4 18.49 180 top
CE21  -  [C_0402]  154.38 20.07 180 bottom
CE22  -  [C_0603]  164.02 21.53 180 bottom
CE23  -  [C_0402]  163.9 12.1 270 top
CE26  -  [C_0402]  176.08 11.23 90 top
CE27  -  [C_0402]  25.25 70.76 270 bottom
CE28  -  [C_0402]  181.71 21.64 90 bottom
CE29  -  [C_0402]  200.72 21.65 90 bottom
CE30  -  [C_0402]  180.82 21.64 90 bottom
CE31  -  [C_0402]  189.78 21.64 90 bottom
CE32  -  [C_0402]  178.81 21.65 90 bottom
CE33  -  [C_0402]  188.76 21.64 90 bottom
CE34  -  [C_0402]  179.83 21.65 90 bottom
CE35  -  [C_0402]  191.81 21.64 90 bottom
CE36  -  [C_0402]  182.73 21.64 90 bottom
CE37  -  [C_0402]  190.79 21.64 90 bottom
CE38  -  [C_0402]  192.76 21.64 90 bottom
CE39  -  [C_0402]  186.73 21.64 90 bottom
CE40  -  [C_0402]  176.78 21.65 90 bottom
CE41  -  [C_0402]  197.8 21.65 90 bottom
CE42  -  [C_0402]  175.83 21.65 90 bottom
CE43  -  [C_0402]  184.76 21.64 90 bottom
CE44  -  [C_0402]  194.75 21.65 90 bottom
CE45  -  [C_0402]  185.71 21.64 90 bottom
CE46  -  [C_0402]  196.78 21.65 90 bottom
CE47  -  [C_0402]  183.74 21.64 90 bottom
CE48  -  [C_0402]  177.8 21.65 90 bottom
CE49  -  [C_0402]  195.77 21.65 90 bottom
CE50  -  [C_0402]  193.8 21.65 90 bottom
CE51  -  [C_0402]  198.82 21.65 90 bottom
CE52  -  [C_0402]  187.74 21.64 90 bottom
CE53  -  [C_0402]  199.77 21.65 90 bottom
CE57  -  [C_0603]  28.94 67.11 270 bottom
CE58  -  [C_0402]  172.93 22.56 270 bottom
CE322  -  [C_0603]  173.23 11.31 90 top
CH1  -  [C_0402]  277.74 34.76 270 top
CH2  -  [C_0402]  277.81 30.99 90 top
CH3  -  [C_0402]  277.63 20.84 0 top
CH4  -  [C_0402]  276.76 20.84 180 top
CH5  -  [C_0603]  261.5 51.12 180 bottom
CH6  -  [C_0603]  263.91 51.12 180 bottom
CH11  -  [C_0402]  239.61 15.78 90 bottom
CH12  -  [C_0603]  258.7 57.73 270 top
CH13  -  [C_0402]  278.42 39.66 90 bottom
CH14  -  [C_0402]  270 42.54 90 bottom
CH17  -  [C_0402]  255.27 24.44 180 top
CH18  -  [C_0402]  255.27 25.33 180 top
CH19  -  [C_0402]  252.48 37.03 0 bottom
CH20  -  [C_0402]  252.48 37.92 0 bottom
CH21  -  [C_0402]  252.48 39.7 0 bottom
CH22  -  [C_0402]  252.48 38.81 0 bottom
CH23  -  [C_0402]  100.91 37.03 180 bottom
CH24  -  [C_0402]  269.89 32.46 180 top
CH25  -  [C_0402]  100.91 37.92 180 bottom
CH26  -  [C_0402]  279.59 36.63 90 top
CH27  -  [C_0402]  262.32 43.51 180 bottom
CH28  -  [C_0402]  263.19 43.51 0 bottom
CH29  -  [C_0402]  100.9 38.88 180 bottom
CH30  -  [C_0402]  265.92 37.47 0 top
CH31  -  [C_0402]  100.9 40.78 180 bottom
CH32  -  [C_0402]  100.9 39.77 180 bottom
CH33  -  [C_0402]  269.96 34.03 90 top
CH35  -  [C_0805]  265.51 30.86 270 top
CH36  -  [C_0402]  267.29 31.49 90 top
CH37  -  [C_0402]  265.5 32.33 0 top
CH38  -  [C_0402]  263.99 29.36 270 top
CH40  -  [C_0402]  100.9 41.67 180 bottom
CH41  -  [C_0402]  100.9 43.58 180 bottom
CH42  -  [C_0402]  100.9 42.69 180 bottom
CH43  -  [C_0402]  100.91 35.06 180 bottom
CH44  -  [C_0402]  100.91 35.95 180 bottom
CH46  -  [C_0402]  260.86 36.78 180 top
CH54  -  [C_0402]  265.69 26.05 270 top
CH55  -  [C_0402]  276.16 28.47 270 top
CH56  -  [C_0402]  274.69 26.3 0 top
CH60  -  [C_0805]  254.03 36.14 180 top
CH61  -  [C_0402]  262.97 34.73 90 top
CH62  -  [C_0402]  263.94 33.09 180 top
CH63  -  [C_0603]  257.68 41.1 180 top
CH64  -  [C_0603]  275.14 27.38 180 top
CH65  -  [C_0805]  270.06 44.49 270 top
CH66  -  [C_0805]  255.45 33.12 270 top
CH67  -  [C_0805]  254.03 32.57 180 top
CH68  -  [C_0805]  255.45 34.47 90 top
CH69  -  [C_0402]  267.75 29.28 180 top
CH70  -  [C_0402]  268.18 30.73 90 top
CH71  -  [C_0402]  271.78 19.77 270 top
CH72  -  [C_0402]  260.13 30.79 180 top
CH73  -  [C_0402]  265.01 26.93 180 top
CH75  -  [C_0603]  268.53 42.18 270 top
CH76  -  [C_0402]  261.38 27.44 180 top
CH77  -  [C_0402]  269.93 28.6 270 top
CH78  -  [C_0402]  260.99 30.81 0 top
CH79  -  [C_0402]  268.98 28.44 90 top
CH81  -  [C_0805]  254.03 34.35 180 top
CH82  -  [C_0402]  268.15 34.11 315 top
CH84  -  [C_0402]  268.16 36.9 0 top
CH85  -  [C_0402]  265.89 27.18 90 top
CH86  -  [C_0402]  267.66 39.7 0 top
CH87  -  [C_0603]  259.23 20.47 180 top
CH88  -  [C_0402]  263.21 26.94 180 top
CH89  -  [C_0402]  263.33 25.75 270 top
CH90  -  [C_0402]  278.95 24.6 270 top
CH91  -  [C_0402]  275.15 24.02 180 top
CH92  -  [C_0402]  279.84 24.6 270 top
CH93  -  [C_0402]  275.34 32.84 180 top
CH94  -  [C_0402]  267.9 26.87 90 top
CH95  -  [C_0402]  261.73 28.46 0 top
CH98  -  [C_0402]  262.03 33.54 270 top
CH99  -  [C_0402]  254.13 53.68 270 top
CH100  -  [C_0402]  271.66 30.81 0 top
CH101  -  [C_0402]  261.32 41.27 90 top
CH102  -  [C_0603]  260.22 41.04 90 top
CH103  -  [C_0402]  267.29 35.49 90 top
CH104  -  [C_0402]  271.78 32.4 0 top
CH105  -  [C_0402]  264.8 33.98 0 top
CH106  -  [C_0402]  265.12 39.77 180 top
CH107  -  [C_0402]  270.84 33.4 90 top
CH108  -  [C_0402]  271.78 33.32 0 top
CH109  -  [C_0402]  268.16 35.51 0 top
CH110  -  [C_0402]  265.95 35.84 270 top
CH111  -  [C_0402]  263.92 33.97 90 top
CI1  -  [C_1206]  18.58 62.24 270 top
CI2  -  [C_0402]  17.11 62.8 90 top
CI3  -  [C_0402]  23.89 57.55 180 top
CI4  -  [C_0402]  23.89 58.44 180 top
CI5  -  [C_0402]  32.12 57.68 180 top
CI6  -  [C_0402]  32.12 58.57 180 top
CI7  -  [C_0402]  32.12 59.45 180 top
CI8  -  [C_0402]  32.12 60.34 180 top
CI9  -  [C_1206]  20.55 77.17 90 bottom
CI11  -  [C_0402]  32.12 62.13 180 top
CI12  -  [C_0402]  32.12 63.02 180 top
CI13  -  [C_0402]  32.12 63.91 180 top
CI15  -  [C_0402]  21.68 76.02 0 bottom
CI16  -  [C_0402]  23.78 69.27 90 top
CI17  -  [C_0402]  24.67 69.27 90 top
CI19  -  [C_0805]  19.39 62 270 bottom
CI20  -  [C_0402]  32.12 64.8 180 top
CI23  -  [C_0805]  21.82 74.51 0 bottom
CI24  -  [C_0402]  28.26 51.32 90 top
CI26  -  [C_0402]  23.35 76.89 180 bottom
CI27  -  [C_0402]  29.64 62.88 180 bottom
CI50  -  [C_0402]  26.53 60.97 270 bottom
CLRP1  -  [SHORTPADS]  260.36 49.34 270 bottom
CLRP2  -  [SHORTPADS]  263.65 49.3 90 bottom
CM11  -  [C_0402]  281.75 40.38 90 top
CM12  -  [C_0402]  280.22 14.63 270 top
CM13  -  [C_0402]  281.11 14.61 270 top
CM14  -  [C_0805]  280.6 40.4 135 bottom
CM22  -  [C_0402]  258.62 12.01 270 top
CM30  -  [C_0402]  252.68 13.77 270 top
CM31  -  [C_0402]  251.79 13.77 270 top
CM32  -  [C_0603]  253.8 14.26 270 top
CM33  -  [C_0402]  251.12 9.79 180 bottom
CN1  -  [C_0402]  30.67 28.6 270 bottom
CN2  -  [C_0402]  29.78 28.6 270 bottom
CN3  -  [C_0402]  31.55 28.46 0 bottom
CN4  -  [C_0402]  29.76 25.79 0 bottom
CN5  -  [C_0402]  29.76 24.9 0 bottom
CN6  -  [C_0402]  29.76 26.68 0 bottom
CN7  -  [C_0805]  38.27 31.04 90 top
CN8  -  [C_0402]  31.36 33.54 180 bottom
CN9  -  [C_0402]  31.36 34.43 180 bottom
CN10  -  [C_0402]  40.06 34.56 180 bottom
CN11  -  [C_0402]  40.06 33.67 180 bottom
CN12  -  [C_0402]  31.36 36.21 180 bottom
CN13  -  [C_0402]  31.36 35.32 180 bottom
CN14  -  [C_0603]  226.03 59.27 180 top
CN15  -  [C_0402]  226.1 60.36 180 top
CN18  -  [C_0402]  40.06 35.45 180 bottom
CN19  -  [C_0402]  40.06 36.33 180 bottom
CN28  -  [C_0402]  41.57 32.78 0 bottom
CN29  -  [C_0402]  32.5 39.73 270 bottom
CN34  -  [C_0603]  70.67 32.33 180 bottom
CT21  -  [C_0402]  95.77 40.84 180 top
CT22  -  [C_0603]  96.84 42.62 90 top
CT44  -  [C_0402]  91.88 42.1 90 top
CU1  -  [C_0402]  196.06 102.58 0 bottom
CU2  -  [C_0402]  198.22 101.52 0 bottom
CU3  -  [C_0402]  196.06 100.47 0 bottom
CU4  -  [C_0402]  198.22 99.42 0 bottom
CU5  -  [C_0402]  196.06 98.37 0 bottom
CU6  -  [C_0402]  198.22 96.44 0 bottom
CU7  -  [C_0402]  196.06 96.28 0 bottom
CU8  -  [C_0402]  198.22 95.23 0 bottom
CU9  -  [C_0402]  196.06 94.18 0 bottom
CU10  -  [C_0402]  198.22 93.13 0 bottom
CU11  -  [C_0402]  196.06 92.09 0 bottom
CU12  -  [C_0402]  198.22 91.04 0 bottom
CU13  -  [C_0402]  196.06 89.1 0 bottom
CU14  -  [C_0402]  198.22 88.94 0 bottom
CU15  -  [C_0402]  196.06 87.01 0 bottom
CU16  -  [C_0402]  198.22 86.85 0 bottom
CU17  -  [C_0402]  196.06 101.67 0 bottom
CU18  -  [C_0402]  198.22 100.63 0 bottom
CU19  -  [C_0402]  196.06 99.58 0 bottom
CU20  -  [C_0402]  198.22 98.53 0 bottom
CU21  -  [C_0402]  196.06 97.48 0 bottom
CU22  -  [C_0402]  198.22 97.32 0 bottom
CU23  -  [C_0402]  196.06 95.39 0 bottom
CU24  -  [C_0402]  198.22 94.34 0 bottom
CU25  -  [C_0402]  196.06 93.29 0 bottom
CU26  -  [C_0402]  198.22 92.24 0 bottom
CU27  -  [C_0402]  196.06 91.2 0 bottom
CU28  -  [C_0402]  198.22 90.15 0 bottom
CU29  -  [C_0402]  196.06 89.99 0 bottom
CU30  -  [C_0402]  198.22 88.05 0 bottom
CU31  -  [C_0402]  196.06 87.89 0 bottom
CU32  -  [C_0402]  198.22 85.96 0 bottom
CU36  -  [C_0402]  139.99 103.9 0 bottom
CU39  -  [C_0402]  140.54 66.3 180 bottom
CU168  -  [C_D2]  172.82 64.46 0 bottom
CU169  -  [C_0603]  164.02 80.82 180 top
CU170  -  [C_0603]  165.22 82.72 0 top
CU171  -  [C_0603]  167.13 81.48 0 top
CU172  -  [C_0603]  170.05 81.48 0 top
CU173  -  [C_0603]  167.63 82.72 0 top
CU174  -  [C_0603]  154.81 81.67 180 top
CU175  -  [C_0603]  158.03 69.61 270 top
CU176  -  [C_0603]  159.3 69.61 270 top
CU177  -  [C_0402]  169.67 68.38 90 top
CU178  -  [C_0402]  168.72 68.38 90 top
CU192  -  [C_0402]  152.21 80 90 top
CU193  -  [C_0402]  156.67 82.37 180 top
CU194  -  [C_0402]  156.67 81.48 180 top
CU195  -  [C_0402]  157.54 81.4 90 top
CU196  -  [C_0402]  159.71 81.54 180 top
CU197  -  [C_0402]  159.71 82.49 180 top
CU198  -  [C_0402]  161.62 81.54 180 top
CU199  -  [C_0402]  161.62 82.49 180 top
CU200  -  [C_0402]  163.97 81.99 180 top
CU201  -  [C_0402]  163.96 82.91 180 top
CV26  -  [C_0603]  57.89 39.25 270 bottom
CV32  -  [C_0402]  12.25 91.97 270 bottom
CV531  -  [C_0402]  199.95 85.99 180 top
CV532  -  [C_0402]  199.95 85.11 180 top
CV533  -  [C_0402]  201.85 84.85 180 top
CV534  -  [C_0402]  201.85 83.96 180 top
CV535  -  [C_0402]  201.85 86.25 180 top
CV536  -  [C_0402]  201.85 87.14 180 top
CV537  -  [C_0402]  199.95 87.39 180 top
CV538  -  [C_0402]  199.95 88.28 180 top
CV539  -  [C_0402]  201.85 88.53 180 top
CV540  -  [C_0402]  201.85 89.42 180 top
CV541  -  [C_0402]  199.95 89.68 180 top
CV542  -  [C_0402]  199.95 90.57 180 top
CV543  -  [C_0402]  201.85 90.82 180 top
CV544  -  [C_0402]  201.85 91.71 180 top
CV545  -  [C_0402]  199.95 92.85 180 top
CV546  -  [C_0402]  199.95 91.96 180 top
CV547  -  [C_0402]  201.85 93.11 180 top
CV548  -  [C_0402]  201.85 94 180 top
CV550  -  [C_0402]  199.95 94.25 180 top
CV551  -  [C_0402]  199.95 95.14 180 top
CV552  -  [C_0402]  201.85 97.68 180 top
CV557  -  [C_0402]  201.85 98.57 180 top
CV558  -  [C_0402]  199.95 97.42 180 top
CV559  -  [C_0402]  199.95 96.54 180 top
CV560  -  [C_0402]  201.85 96.28 180 top
CV561  -  [C_0402]  201.85 95.39 180 top
CV562  -  [C_0402]  199.95 98.82 180 top
CV563  -  [C_0402]  199.95 99.71 180 top
CV564  -  [C_0402]  201.85 100.85 180 top
CV565  -  [C_0402]  201.85 99.96 180 top
CV566  -  [C_0402]  199.95 102 180 top
CV567  -  [C_0402]  199.95 101.11 180 top
CV568  -  [C_0402]  209.82 84.57 0 top
CV569  -  [C_0402]  209.8 85.97 90 top
CV570  -  [C_0402]  210.69 85.97 90 top
CV571  -  [C_0402]  209.82 83.68 0 top
CV572  -  [C_0603]  209.55 78.18 0 top
CV573  -  [C_0805]  209.52 79.7 0 top
CV574  -  [C_0805]  213.45 82.3 180 top
CV575  -  [C_0402]  226.36 74.56 0 bottom
CV576  -  [C_0402]  225.5 74.56 180 bottom
CV580  -  [C_0402]  209.77 91.42 0 top
CV581  -  [C_0402]  209.77 90.53 0 top
CV582  -  [C_0603]  210.38 93.94 270 top
CV583  -  [C_0603]  205.09 104.44 90 top
CV584  -  [C_0603]  203.89 104.44 90 top
CV585  -  [C_0805]  200.94 79.26 180 top
CV586  -  [C_0805]  200.94 81.03 180 top
CV587  -  [C_0805]  222.92 84.15 0 top
CV588  -  [C_0603]  211.31 99.08 90 top
CV589  -  [C_0603]  223.14 86.88 0 top
CV590  -  [C_0603]  215.2 99.07 270 top
CV591  -  [C_0402]  223.62 97.83 180 top
CV592  -  [C_0402]  219.02 99.39 180 top
CV593  -  [C_0402]  213.22 98.81 0 top
CV594  -  [C_0402]  226.36 106.18 0 top
CV595  -  [C_0402]  209.72 96.09 0 top
CV596  -  [C_0402]  209.72 95.2 0 top
CV597  -  [C_0603]  209.48 97.99 0 top
CV598  -  [C_0603]  206.3 104.44 90 top
CV599  -  [C_0603]  207.5 104.44 90 top
CV600  -  [C_0805]  203.66 82.28 0 top
CV601  -  [C_0805]  203.66 80.53 0 top
CV602  -  [C_0805]  226.8 107.83 0 top
CV603  -  [C_0603]  221.42 102.81 0 top
CV604  -  [C_0603]  220.91 88.97 180 top
CV605  -  [C_0603]  221.42 100.21 0 top
CV606  -  [C_0402]  218.04 103.58 0 top
CV607  -  [C_0402]  223.1 92.72 180 top
CV608  -  [C_0402]  223.09 93.61 180 top
CV609  -  [C_0402]  223.82 89.42 0 top
CV610  -  [C_0402]  208.66 99.56 90 top
CV611  -  [C_0402]  209.8 100.13 90 top
CV612  -  [C_0603]  200.53 103.13 180 top
CV613  -  [C_0402]  207.31 103.45 0 top
CV614  -  [C_0402]  223.89 80.34 0 top
CV615  -  [C_0603]  224.66 76.91 0 top
CV616  -  [C_0603]  224.66 75.7 0 top
CV617  -  [C_0603]  218.12 83.45 180 top
CV619  -  [C_0402]  220.85 82.7 270 top
CV621  -  [C_0402]  221.8 82.7 270 top
CV622  -  [C_0402]  219.96 82.7 270 top
CV623  -  [C_0402]  219.06 83.57 90 top
CV636  -  [C_0402]  223.77 90.93 90 top
CV637  -  [C_0402]  230.92 107.25 90 top
CV638  -  [C_0402]  224.89 99.63 90 top
CV639  -  [C_0402]  230.69 111.62 270 top
CV643  -  [C_0402]  220.78 128.21 0 top
CV650  -  [C_0402]  228.51 120.85 0 top
CV651  -  [C_0402]  219.9 127.33 180 top
CV652  -  [C_0603]  225.23 119.58 0 top
CV653  -  [C_0402]  215.38 127.13 0 top
CV654  -  [C_0402]  218.07 127.13 180 top
CV655  -  [C_0402]  222.55 127.2 0 top
CV656  -  [C_0402]  224.9 122.5 0 top
CV657  -  [C_0402]  217.98 114.56 0 top
CV658  -  [C_0402]  224.33 127.2 0 top
CV659  -  [C_0603]  227.65 126.56 180 top
CV660  -  [C_0402]  223.91 120.15 180 top
CV661  -  [C_0402]  225.41 114.56 0 top
CV662  -  [C_0402]  217.12 114.56 180 top
CV663  -  [C_0402]  223.63 114.56 0 top
CV668  -  [C_0402]  203.71 128.04 270 top
CV675  -  [C_0402]  209.79 123.39 0 top
CV676  -  [C_0402]  204.66 128.04 270 top
CV677  -  [C_0603]  193.76 123.37 270 top
CV678  -  [C_0402]  199.23 128.03 0 top
CV679  -  [C_0402]  206.61 127.13 0 top
CV680  -  [C_0402]  205.79 121.8 0 top
CV681  -  [C_0402]  199.23 127.14 0 top
CV682  -  [C_0402]  194.29 127.06 90 top
CV683  -  [C_0402]  208.47 115.88 90 top
CV684  -  [C_0603]  203.71 114.24 0 top
CV685  -  [C_0402]  198.84 113.36 0 bottom
CV686  -  [C_0402]  205.98 114.56 0 top
CV687  -  [C_0402]  200.84 114.42 180 top
CV688  -  [C_0402]  199.05 114.26 270 top
CV693  -  [C_0402]  255.14 84.98 270 top
CV700  -  [C_0402]  247.06 77.73 270 bottom
CV701  -  [C_0402]  254.77 77.96 0 top
CV702  -  [C_0603]  254.42 91.41 90 top
CV703  -  [C_0402]  252.51 85.33 270 top
CV704  -  [C_0402]  241.34 82.91 270 top
CV705  -  [C_0402]  243.81 81.62 90 top
CV706  -  [C_0402]  241.53 91.27 90 top
CV707  -  [C_0402]  242.73 81.24 90 top
CV708  -  [C_0402]  242.29 88.73 90 top
CV709  -  [C_0603]  241.49 76.97 180 bottom
CV710  -  [C_0402]  254.23 82.6 270 top
CV711  -  [C_0402]  253.27 88.88 270 top
CV712  -  [C_0402]  254.23 84.09 90 top
CV713  -  [C_0402]  254.23 89.49 90 top
CV718  -  [C_0402]  255.71 104.54 270 top
CV725  -  [C_0402]  249.78 114 90 top
CV726  -  [C_0402]  254.85 101.82 0 top
CV727  -  [C_0603]  241.34 99.47 0 top
CV728  -  [C_0402]  243.76 108.43 180 top
CV729  -  [C_0402]  248.73 105.67 90 top
CV730  -  [C_0402]  243.89 103.79 180 top
CV731  -  [C_0402]  250.04 99.72 90 top
CV732  -  [C_0402]  246.26 101.1 180 top
CV733  -  [C_0402]  251.12 112.5 0 top
CV734  -  [C_0603]  252.73 97.04 270 top
CV735  -  [C_0402]  254.34 112.11 90 top
CV736  -  [C_0402]  250.43 96.97 0 top
CV737  -  [C_0402]  241.17 107.5 90 top
CV738  -  [C_0402]  241.34 102.6 270 top
CV743  -  [C_0402]  33.77 97.92 0 top
CV744  -  [C_0402]  33.77 101.86 0 top
CV745  -  [C_0402]  24.97 97.73 180 top
CV751  -  [C_0402]  87.25 37.14 90 top
CV752  -  [C_0402]  81.6 37.32 270 top
CV753  -  [C_0402]  40.69 44.7 180 top
CV754  -  [C_0402]  40.68 43.52 180 top
CV756  -  [C_0402]  25.22 103.2 180 top
CV758  -  [C_0402]  32.74 95.34 270 top
CV759  -  [C_0402]  31.85 95.34 270 top
CV760  -  [C_0402]  30.96 95.34 270 top
CV761  -  [C_0402]  30.07 95.34 270 top
CV762  -  [C_0402]  29.19 95.34 270 top
CV763  -  [C_0402]  28.3 95.34 270 top
CV764  -  [C_0402]  27.41 95.34 270 top
CV765  -  [C_0402]  26.52 95.34 270 top
CV766  -  [C_0402]  14.13 113.22 90 bottom
CV767  -  [C_0603]  15.19 112.39 90 bottom
CV768  -  [C_0402]  15.25 112.4 180 top
CV769  -  [C_0603]  11.41 94.88 0 bottom
CV770  -  [C_0402]  11.33 92.91 0 bottom
CV771  -  [C_0402]  33.77 97.04 0 top
CV772  -  [C_0402]  24.97 96.78 180 top
CV773  -  [C_0402]  211.71 85.11 270 top
CV774  -  [C_0402]  33.77 98.81 0 top
CV775  -  [C_0402]  33.77 102.81 0 top
CV776  -  [C_0402]  228.51 119.96 0 top
CV777  -  [C_0402]  209.79 122.5 0 top
CV778  -  [C_0402]  249.43 93.66 90 top
CV779  -  [C_0402]  31.05 73.36 270 bottom
CV780  -  [C_0402]  30.16 73.36 270 bottom
CV781  -  [C_0402]  29.27 73.36 270 bottom
CV782  -  [C_0402]  28.38 73.36 270 bottom
CV783  -  [C_0402]  27.49 73.36 270 bottom
CV784  -  [C_0402]  26.6 73.36 270 bottom
CV785  -  [C_0402]  25.71 73.36 270 bottom
CV786  -  [C_0402]  24.8 73.36 270 bottom
CV787  -  [C_0805]  11.25 96.41 0 bottom
CV788  -  [C_0402]  11.33 93.8 0 bottom
CV789  -  [C_0402]  250.67 114 90 top
CV795  -  [C_0402]  15.25 111.45 180 top
CV796  -  [C_0402]  15.25 110.5 180 top
CV812  -  [C_0402]  32.83 73.36 270 bottom
CV813  -  [C_0402]  31.94 73.36 270 bottom
CV3501  -  [C_0402]  81.8 39.89 180 top
CV3508  -  [C_0805]  82.97 40.52 0 top
CV3509  -  [C_0402]  196.19 70.1 90 bottom
CV3512  -  [C_0402]  233.16 110.57 180 top
CV3513  -  [C_0805]  231.98 107.71 0 top
CZ6  -  [C_0402]  210.74 69.41 0 bottom
CZ7  -  [C_0402]  214.3 64.14 0 top
CZ8  -  [C_0402]  210.75 70.32 0 bottom
CZ11  -  [C_0805]  40.98 48.26 90 bottom
CZ15  -  [C_0603]  36.55 44.72 270 top
CZ20  -  [C_0805]  28.54 47.7 90 bottom
CZ28  -  [C_0603]  33.91 42.74 180 bottom
CZ29  -  [C_0603]  39.34 41.82 0 bottom
CZ32  -  [C_0603]  220.28 14.83 270 bottom
CZ38  -  [C_0603]  35.31 44.72 270 top
CZ45  -  [C_0805]  222.9 15.06 90 bottom
CZ600  -  [C_0603]  257.34 50.56 0 top
CZ601  -  [C_0603]  255.5 51.57 180 top
CZ602  -  [C_0402]  259.69 52.9 90 top
D8  -  [PESD24VS2UT_SOT23-3]  4.38 33.18 180 bottom
DA2  -  [PJDLC05_SOT23-3]  17.44 44.28 270 bottom
DA3  -  [PJDLC05_SOT23-3]  15.17 32.85 0 top
DA4  -  [PJDLC05C_SOT23-3]  7.94 9.94 0 bottom
DA5  -  [PJDLC05C_SOT23-3]  7.16 7.02 180 top
DE2  -  [PESD24VS2UT_SOT23-3]  17.19 103.23 270 bottom
DE4  -  [CH751H-40PT_SOD323-2]  28.64 69.61 180 bottom
DE5  -  [PESD5V0U2BT_SOT23-3]  211.05 21.98 270 top
DE6  -  [PESD5V0U2BT_SOT23-3]  213.13 18.04 90 top
DE7  -  [RB751V40_SC76-2]  190.73 11.88 0 top
DE8  -  [RB751V40_SC76-2]  174.75 13.55 270 top
DE9  -  [RB751V40_SC76-2]  178.43 13.55 270 top
DE10  -  [RB751V40_SC76-2]  189.12 11.88 180 top
DE12  -  [RB751V40_SC76-2]  143.04 11.82 0 top
DE13  -  [RB751V40_SC76-2]  190.73 15.31 0 top
DE14  -  [RB751V40_SC76-2]  190.73 13.6 0 top
DE15  -  [RB751V40_SC76-2]  189.12 15.31 180 top
DE16  -  [RB751V40_SC76-2]  189.12 13.6 180 top
DE17  -  [RB751V40_SC76-2]  190.73 17.03 0 top
DE18  -  [RB751V40_SC76-2]  189.12 17.03 180 top
DE303  -  [RB751V40_SC76-2]  184.3 17.6 180 top
DE304  -  [RB751V40_SC76-2]  169.9 11.69 0 top
DE305  -  [RB751V40_SC76-2]  184.3 15.88 180 top
DE306  -  [RB751V40_SC76-2]  189.12 18.74 180 top
DI1  -  [AZ1045-04F_DFN2510P10E-10-9]  18.66 56.09 90 top
DI2  -  [AZC199-02SPR7G_SOT23-3]  22.07 59.41 0 bottom
DI3  -  [PESD5V0U2BT_SOT23-3]  23.94 117.15 90 bottom
DI5  -  [AZC199-02SPR7G_SOT23-3]  23.11 71.04 270 bottom
DI6  -  [AZ1045-04F_DFN2510P10E-10-9]  18.6 70.57 90 top
DN2  -  [PESD5V0U2BT_SOT23-3]  247.17 11.63 90 top
DPF1  -  [F_1206L150PR]  13.44 98.44 180 bottom
DV2  -  [AZ1045-04F_DFN2510P10E-10-9]  15.17 88.03 90 top
DV3  -  [AZ1045-04F_DFN2510P10E-10-9]  14.29 93.53 270 top
DV4  -  [AZ1045-04F_DFN2510P10E-10-9]  14.67 109.08 270 top
DV5  -  [AZ1045-04F_DFN2510P10E-10-9]  15.55 103.72 90 top
DV8  -  [BAT1000-7-F_SOT23-3]  17.19 107.23 270 bottom
DV9  -  [BAT1000-7-F_SOT23-3]  16.17 98.72 0 bottom
DV10  -  [BAT54CW-7-F_SOT323-3]  86.55 32.33 180 bottom
DV11  -  [RB751V40_SC76-2]  19.33 101.56 90 bottom
DV13  -  [BAT54CW-7-F_SOT323-3]  89.09 32.33 180 bottom
DV17  -  [RB751V40_SC76-2]  16.49 112.35 0 bottom
DV18  -  [RB751V40_SC76-2]  64.46 38.18 0 bottom
DV19  -  [RB751V40_SC76-2]  64.46 39.86 0 bottom
DV20  -  [RB751V40_SC76-2]  16.49 114 0 bottom
DV21  -  [RB751V40_SC76-2]  84.14 32.32 270 top
DZ2  -  [BAT54CW-7-F_SOT323-3]  246.76 56.08 270 top
F1  -  [F_NANOSMDC050F-13P2-2]  221.81 21.75 180 bottom
FD1  -  [FIDUCIAL_C40M80]  254.82 63.57 0 top
FD2  -  [FIDUCIAL_C40M80]  25.59 113.42 0 top
FD3  -  [FIDUCIAL_C40M80]  3.62 6.99 180 bottom
FD4  -  [FIDUCIAL_C40M80]  246.19 122.75 180 bottom
H2  -  [H_2P3]  16.3 118 0 top
H3  -  [H_3P9]  152.52 115.72 0 top
H4  -  [H_3P7]  191.3 105.22 0 top
H5  -  [H_4P1X3P7]  191.3 75.5 90 top
H6  -  [H_3P9]  152.52 65 0 top
H7  -  [EMIST_SUL-12A2M_1P]  17.3 83.9 0 top
H8  -  [H_3P3]  236.8 120 0 top
H9  -  [H_2P3]  253.3 126.5 0 top
H10  -  [H_2P1X2P5]  20.3 118 180 top
H11  -  [H_2P3]  21.8 66 0 top
H12  -  [H_2P5]  151 12.45 0 top
H13  -  [H_2P5]  113.3 126.5 0 top
H14  -  [EMIST_SUL-12A2M_1P]  11.3 84.2 180 bottom
H15  -  [H_3P3]  239.15 70 0 top
H16  -  [H_2P5]  215.6 12.45 0 top
H17  -  [EMIST_SUL-12A2M_1P]  17.3 78.01 90 bottom
H18  -  [H_2P1]  20.3 13.5 0 top
H19  -  [EMIST_SUL-12A2M_1P]  17.31 67 90 bottom
H20  -  [EMIST_SUL-12A2M_1P]  17.3 56 90 bottom
H21  -  [EMIST_SUL-12A2M_1P]  11.31 48.39 180 bottom
H23  -  [EMIST_SUL-12A2M_1P]  17.31 48.6 0 top
H24  -  [EMIST_SUL-12A2M_1P]  29.32 48.6 0 top
H25  -  [EMIST_SUL-12A2M_1P]  35.2 63 270 top
H26  -  [EMIST_SUL-12A2M_1P]  35.2 72.69 270 top
H27  -  [EMIST_SUL-12A2M_1P]  29.31 83.9 0 top
H28  -  [CLIP_C5]  256.3 45.3 180 bottom
H29  -  [CLIP_C5]  275.3 16.7 180 bottom
HDMIF1  -  [F_1206L150PR]  14.5 110.41 0 bottom
HT1  -  [R_0402]  107.3 53.53 90 bottom
HT2  -  [R_0402]  191.8 128.03 0 bottom
HT3  -  [R_0402]  179.72 53.35 90 bottom
HT4  -  [R_0402]  190.55 80.91 180 top
HT5  -  [R_0402]  254.65 123.1 0 bottom
HT6  -  [R_0402]  111.98 123.1 180 bottom
HU101  -  [R_0402]  150.07 86.37 90 top
JDIMM1  -  [BELLW_80001-1021_204P]  108.9 34.3 180 bottom
JDIMM2  -  [BELLW_80001-1021_204P]  183.4 34.3 180 bottom
JEDP1  -  [ACES_59003-04006-001_40P]  92.05 40.82 0 bottom
JFAN1  -  [ACES_50224-00401-001_4P]  51.1 34.42 0 bottom
JHDD  -  [J-L_UCNR2234B020-0_20P]  27.54 32.86 270 bottom
JHDMI  -  [ACON_HMRB9-AK120C_19P-T]  11.77 104.7 270 top
JHP2  -  [SINGA_2SJ3095-001111F_6P-T]  12.27 46.64 90 top
JKB  -  [ACES_50692-03041-001_30P]  200.77 20.08 180 bottom
JKBL  -  [ACES_50524-00401-001_4P-T]  232.8 21.2 180 bottom
JMDP  -  [ACON_MAR2H-20K1200_20P-T]  11.42 89.01 270 top
JNFC1  -  [HB_A531515-SCHR21_15P-T]  122.8 19.32 180 bottom
JP2  -  [JUMP_43X39]  263.94 30.88 180 top
JP3  -  [JUMP_43X118]  173.86 68.48 90 top
JP4  -  [JUMP_43X118]  164.91 68.55 90 top
JP5  -  [JUMP_43X118]  253.1 41.21 270 top
JP6  -  [JUMP_43X39]  273.99 29.15 0 top
JP7  -  [JUMP_43X39]  260.34 50.62 0 top
JP8  -  [JUMP_43X39]  4.71 30.81 180 bottom
JP9  -  [JUMP_43X39]  22.97 43.44 0 bottom
JP10  -  [JUMP_43X39]  13.41 29.5 270 top
JP11  -  [JUMP_43X39]  250.67 44.17 270 top
JP12  -  [JUMP_43X39]  280.43 40.9 180 top
JP13  -  [JUMP_43X39]  30.92 30.26 0 bottom
JP14  -  [JUMP_43X39]  224.93 15.83 270 bottom
JP15  -  [JUMP_43X118]  62.12 34.76 0 bottom
JP17  -  [JUMP_43X39]  263.73 14.16 90 top
JP18  -  [JUMP_43X39]  269.47 20.21 0 top
JP19  -  [JUMP_43X39]  268.03 44.41 270 top
JP802  -  [JUMP_43X118]  40.36 45.07 180 bottom
JP803  -  [JUMP_43X118]  32.02 45.98 0 bottom
JSPK1  -  [ACES_50224-00401-001_4P]  9.08 5.56 180 bottom
JSSD  -  [ACES_50711-0520W-001_52P]  281.62 14.6 270 bottom
JTB1  -  [HRS_DF40HC-3P0-90DS-04V_90P-T]  270.9 12.57 180 bottom
JTP  -  [ACES_50506-00841-P01_8P]  209.75 22.98 180 bottom
JTS  -  [ACES_50208-00601-P01_6P]  20 108.99 270 bottom
JUSB1  -  [TAIWI_USB019-107CRL-TWD_10P-T]  13.6 60.21 270 top
JUSB3  -  [TAIWI_USB019-107CRL-TWD_10P-T]  13.6 78.71 270 top
JXDP  -  [SAMTE_BSH-030-01-L-D-A-TR_60P]  139.81 98.05 90 top
L1  -  [MURAT_BLM18AG601SN1D_L0603_2P]  217.26 20.84 180 top
L2  -  [MURAT_BLM18AG601SN1D_L0603_2P]  217.26 22.99 180 top
LA1  -  [MURAT_BLM21PG600SN1D_L0805_2P]  21.74 48.59 180 bottom
LA3  -  [TAIYO_NRH3010T4R7MN_2P]  26.9 32.14 0 top
LA5  -  [MURAT_BLM15GA750SN1D_2P]  15.89 44.84 180 top
LA6  -  [MURAT_BLM15GA750SN1D_2P]  15.88 38.3 180 top
LA7  -  [MURAT_BLM18PG181SN1D_2P]  15.17 17.94 270 bottom
LA8  -  [MURAT_BLM18PG181SN1D_2P]  2.86 19.78 270 bottom
LA9  -  [MURAT_BLM18PG181SN1D_2P]  12.63 17.43 270 bottom
LA11  -  [MURAT_BLM18PG181SN1D_2P]  4.32 17.43 270 bottom
LE1  -  [KC_FBMA-L11-160808-800LMT_2P]  156.6 22.42 0 top
LE2  -  [KC_FBMA-L11-160808-800LMT_2P]  158.1 20.9 180 top
LED3  -  [LED_12-22-Y2BHC-A30-2C_3P]  2.35 27.55 90 top
LED6  -  [LED_LTW-270TLA_2P]  2.01 10.04 90 top
LED7  -  [LED_LTW-270TLA_2P]  2.01 20.84 90 top
LED8  -  [LED_LTW-270TLA_2P]  2.01 17.22 90 top
LED9  -  [LED_LTW-270TLA_2P]  2.01 13.66 90 top
LH100  -  [MURAT_LQM18FN4R7M00D_2P]  258.89 42.31 270 top
LI1  -  [MURAT_DLW21SN900HQ2L_0805_4P]  24.72 56.74 90 bottom
LI2  -  [MURAT_DLW21SN900HQ2L_0805_4P]  21.8 58.47 180 top
LI3  -  [MURAT_DLW21SN900HQ2L_0805_4P]  21.8 56.76 180 top
LI4  -  [MURAT_DLW21SN900HQ2L_0805_4P]  28.1 105.56 180 bottom
LI7  -  [MURAT_DLW21SN900HQ2L_0805_4P]  17.38 76.07 270 top
LI8  -  [MURAT_DLW21SN900HQ2L_0805_4P]  21.8 72.76 180 top
LI9  -  [MURAT_DLW21SN900HQ2L_0805_4P]  21.8 71.11 180 top
LV2  -  [MURAT_BLM18PG181SN1D_L0603_2P]  209.55 77 270 top
LV3  -  [MURAT_BLM18AG121SN1D_L0603_2P]  200.4 105.51 270 top
LV7  -  [MURAT_DLW21SN900HQ2L_0805_4P]  26.73 118.42 180 top
LV8  -  [MURAT_DLW21SN900HQ2L_0805_4P]  26.73 116.76 180 top
LV9  -  [MURAT_DLW21SN900HQ2L_0805_4P]  20.66 99.62 180 top
LV10  -  [MURAT_DLW21SN900HQ2L_0805_4P]  20.66 97.91 180 top
LV14  -  [MURAT_BLM18PG300SN1D_2P]  213.23 80.87 270 top
LV16  -  [MURAT_DLP11SN900HL2L_4P]  99.01 37.15 180 bottom
LV17  -  [MURAT_DLP11SN900HL2L_4P]  98.99 39.05 180 bottom
LV18  -  [MURAT_DLP11SN900HL2L_4P]  99.04 35.24 180 bottom
LV19  -  [MURAT_DLP11SN900HL2L_4P]  99.01 40.88 180 bottom
LV20  -  [MURAT_DLP11SN900HL2L_4P]  99.04 42.79 180 bottom
LV21  -  [MURAT_BLM18PG300SN1D_2P]  233.24 109.36 180 top
NOREF  -  []  191.3 105.22 0 top
NOREF#2  -  []  127.32 -11.45 0 top
NOREF#3  -  []  133.51 -28.8 0 top
NOREF#4  -  []  152.52 115.72 0 top
NOREF#5  -  []  236.8 120 0 top
NOREF#6  -  []  134.81 -17.54 0 top
NOREF#7  -  []  253.3 126.5 0 top
NOREF#8  -  []  151 12.45 0 top
NOREF#9  -  []  152.52 65 0 top
NOREF#10  -  []  191.3 75.5 0 top
NOREF#11  -  []  102.37 -59.96 0 top
NOREF#12  -  []  130.29 -35.25 0 top
NOREF#13  -  []  16.3 118 0 top
NOREF#14  -  []  215.6 12.45 0 top
NOREF#15  -  []  239.15 70 0 top
NOREF#16  -  []  113.3 126.5 0 top
NOREF#17  -  []  21.8 66 0 top
NOREF#18  -  []  151.42 -26.92 0 top
NOREF#19  -  []  113.66 211.04 0 top
NOREF#20  -  [unnamed#2]  8.5 16.3 0 top
NOREF#21  -  []  16.3 215.2 0 top
NOREF#22  -  []  124.55 -19.88 180 bottom
NOREF#23  -  []  109.97 -30.08 180 bottom
NOREF#24  -  []  221.63 -106.23 180 bottom
NOREF#25  -  []  171.6 55.48 180 bottom
PC100  -  [C_0402]  22.55 87.89 180 bottom
PC101  -  [C_0402]  22.55 87 180 bottom
PC102  -  [C_0402]  58.1 28.99 270 bottom
PC103  -  [C_0402]  59.25 28.23 270 top
PC104  -  [C_0402]  100.75 28.57 0 bottom
PC105  -  [C_0402]  100.72 29.48 0 bottom
PC106  -  [C_0402]  109.97 22.33 0 bottom
PC107  -  [C_0402]  109.99 23.32 0 bottom
PC108  -  [C_0603]  121.09 13.34 270 top
PC109  -  [C_0402]  115.26 13.72 180 top
PC110  -  [C_0402]  114.35 12.77 0 top
PC111  -  [C_0402]  163.01 11.85 270 top
PC120  -  [C_0402]  22.55 86.11 180 bottom
PC121  -  [C_0402]  33.06 88.81 0 top
PC130  -  [C_0402]  28.82 85.94 270 bottom
PC200  -  [C_0402]  66.05 28.43 180 bottom
PC202  -  [C_0402]  69.79 25.51 0 top
PC203  -  [C_0402]  69.79 24.5 0 top
PC204  -  [C_0805]  71.91 20.74 0 top
PC205  -  [C_0805]  71.96 17.16 0 bottom
PC206  -  [C_0805]  71.91 18.96 0 top
PC207  -  [C_0805]  71.91 17.18 0 top
PC208  -  [C_0402]  64.68 30.95 270 bottom
PC209  -  [C_0603]  80.18 34.23 270 bottom
PC210  -  [C_0402]  79.11 32.27 180 bottom
PC211  -  [C_0402]  77.25 33.21 90 bottom
PC212  -  [C_0603]  75.86 26.62 270 bottom
PC213  -  [C_0402]  70.52 30.04 90 bottom
PC214  -  [C_0805]  75.82 30.72 90 bottom
PC215  -  [C_0805]  92.3 22.87 0 top
PC216  -  [C_0603]  75.44 29.47 180 bottom
PC217  -  [C_0805]  113.03 65.57 180 bottom
PC218  -  [C_0402]  83.15 29.85 0 bottom
PC219  -  [C_0402]  80.86 28.97 0 top
PC220  -  [C_0402]  99.33 15.04 90 top
PC221  -  [C_0805]  101.08 13.79 270 top
PC222  -  [C_0805]  99.3 13.79 270 top
PC223  -  [C_0805]  102.86 13.79 270 top
PC224  -  [C_0603]  77 16.97 90 top
PC225  -  [C_0402]  79.72 26.89 270 top
PC226  -  [C_0402]  79.34 24.52 0 top
PC227  -  [C_0402]  80.66 25.97 90 top
PC228  -  [C_0402]  84.06 25.92 180 top
PC230  -  [C_0805]  113.03 67.42 180 bottom
PC231  -  [C_0805]  92.3 21.09 0 top
PC232  -  [C_0805]  92.28 19.23 0 top
PC233  -  [C_0805]  92.28 17.45 0 top
PC250  -  [C_0402]  114.29 19.69 0 top
PC251  -  [C_0402]  116.08 16.38 90 top
PC252  -  [C_0402]  114.16 15.25 0 top
PC260  -  [C_0402]  59.88 35.21 90 bottom
PC261  -  [C_0603]  43.53 38.62 180 bottom
